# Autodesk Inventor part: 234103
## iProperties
Created: 2006-08
Part Number: 234103
Material: 8.8 vz
Description: Sechskantschraube
Vendor: Autodesk Inc.
Document SubType Name: Modeling
Standard: DIN 933
Designer: I.Baliuc
Standards Organization: DIN
Language: de-DE
Size Designation: M8 x 12
Categories: <MemberInstance Version="R10.0.0"><Categories><Category DisplayName="Schrauben" InternalName="e4da775c-781d-43d5-af7c-5136215cf5a6" Mnemonic="FSTN"><Category Di
Density: 7.85 g/cm^3
Mass: 10.3272 g
Surface Area: 8.11246 cm^2
Volume: 1.31556 cm^3
Abmessung: M8 x 12
Author: T.Messerschmitt
Comments: DIN 933 - M8 x 12
Revision Number: 234103
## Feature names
1. Körper [Revolution]
2. Kopf [Extrusion]
3. Fase1 [Revolution]
4. Fase2 [Chamfer]
